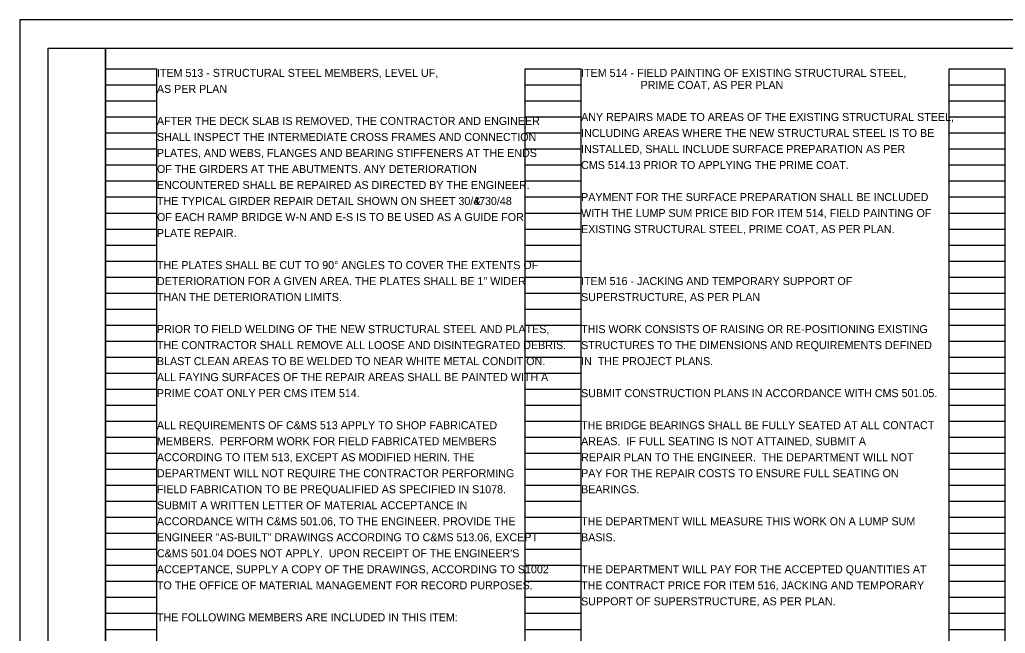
# Model space of a CAD drawing. Extents: x 0 to 34, y 0 to 22.
# Drawn here: x 0 to 17.24, y 11.27 to 22 of the extents above; entities that cross this region are included whole.
import ezdxf

# ---------------------------------------------------------------- set-up
doc = ezdxf.new("R2010")
doc.units = 0
for name, color, linetype in [('BR_P_Gen_Text', 7, 'Continuous'), ('SH_Border', 7, 'Continuous'), ('SH_Cut_Line', 7, 'Continuous'), ('SH_Data', 7, 'Continuous'), ('SH_Text', 7, 'Continuous')]:
    doc.layers.add(name, color=color, linetype=linetype)

msp = doc.modelspace()

# ---------------------------------------------------------------- linework, layer by layer
at = {"layer": 'SH_Border'}
for points in [[(0.5, 21.5), (1.5, 21.5), (1.5, 0.5), (0.5, 0.5)], [(1.5, 21.5), (33.5, 21.5), (33.5, 0.5), (1.5, 0.5)]]:
    msp.add_lwpolyline(points, close=True, dxfattribs=at)
at = {"layer": 'SH_Cut_Line'}
msp.add_lwpolyline([(0, 0), (34, 0), (34, 22), (0, 22)], close=True, dxfattribs=at)
at = {"layer": 'SH_Data'}
for p, q in [((1.5, 0.98), (1.5, 21.14)), ((1.5, 21.14), (2.4, 21.14)), ((2.4, 0.98), (2.4, 21.14)), ((8.84, 0.98), (8.84, 21.14)), ((8.84, 21.14), (9.82, 21.14)), ((9.82, 0.98), (9.82, 21.14)), ((16.26, 0.98), (16.26, 21.14)), ((16.26, 21.14), (17.24, 21.14)), ((17.24, 0.98), (17.24, 21.14)), ((1.5, 20.86), (2.4, 20.86)), ((8.84, 20.86), (9.82, 20.86)), ((16.26, 20.86), (17.24, 20.86)), ((1.5, 20.58), (2.4, 20.58)), ((8.84, 20.58), (9.82, 20.58)), ((16.26, 20.58), (17.24, 20.58)), ((1.5, 20.3), (2.4, 20.3)), ((8.84, 20.3), (9.82, 20.3)), ((16.26, 20.3), (17.24, 20.3)), ((1.5, 20.02), (2.4, 20.02)), ((8.84, 20.02), (9.82, 20.02)), ((16.26, 20.02), (17.24, 20.02)), ((1.5, 19.74), (2.4, 19.74)), ((8.84, 19.74), (9.82, 19.74)), ((16.26, 19.74), (17.24, 19.74)), ((1.5, 19.46), (2.4, 19.46)), ((8.84, 19.46), (9.82, 19.46)), ((16.26, 19.46), (17.24, 19.46)), ((1.5, 19.18), (2.4, 19.18)), ((8.84, 19.18), (9.82, 19.18)), ((16.26, 19.18), (17.24, 19.18)), ((1.5, 18.9), (2.4, 18.9)), ((8.84, 18.9), (9.82, 18.9)), ((16.26, 18.9), (17.24, 18.9)), ((1.5, 18.62), (2.4, 18.62)), ((8.84, 18.62), (9.82, 18.62)), ((16.26, 18.62), (17.24, 18.62)), ((1.5, 18.34), (2.4, 18.34)), ((8.84, 18.34), (9.82, 18.34)), ((16.26, 18.34), (17.24, 18.34)), ((1.5, 18.06), (2.4, 18.06)), ((8.84, 18.06), (9.82, 18.06)), ((16.26, 18.06), (17.24, 18.06)), ((1.5, 17.78), (2.4, 17.78)), ((8.84, 17.78), (9.82, 17.78)), ((16.26, 17.78), (17.24, 17.78)), ((1.5, 17.5), (2.4, 17.5)), ((8.84, 17.5), (9.82, 17.5)), ((16.26, 17.5), (17.24, 17.5)), ((1.5, 17.22), (2.4, 17.22)), ((8.84, 17.22), (9.82, 17.22)), ((16.26, 17.22), (17.24, 17.22)), ((1.5, 16.94), (2.4, 16.94)), ((8.84, 16.94), (9.82, 16.94)), ((16.26, 16.94), (17.24, 16.94)), ((1.5, 16.66), (2.4, 16.66)), ((8.84, 16.66), (9.82, 16.66)), ((16.26, 16.66), (17.24, 16.66)), ((1.5, 16.38), (2.4, 16.38)), ((8.84, 16.38), (9.82, 16.38)), ((16.26, 16.38), (17.24, 16.38)), ((1.5, 16.1), (2.4, 16.1)), ((8.84, 16.1), (9.82, 16.1)), ((16.26, 16.1), (17.24, 16.1)), ((1.5, 15.82), (2.4, 15.82)), ((8.84, 15.82), (9.82, 15.82)), ((16.26, 15.82), (17.24, 15.82)), ((1.5, 15.54), (2.4, 15.54)), ((8.84, 15.54), (9.82, 15.54)), ((16.26, 15.54), (17.24, 15.54)), ((1.5, 15.26), (2.4, 15.26)), ((8.84, 15.26), (9.82, 15.26)), ((16.26, 15.26), (17.24, 15.26)), ((1.5, 14.98), (2.4, 14.98)), ((8.84, 14.98), (9.82, 14.98)), ((16.26, 14.98), (17.24, 14.98)), ((1.5, 14.7), (2.4, 14.7)), ((8.84, 14.7), (9.82, 14.7)), ((16.26, 14.7), (17.24, 14.7)), ((1.5, 14.42), (2.4, 14.42)), ((8.84, 14.42), (9.82, 14.42)), ((16.26, 14.42), (17.24, 14.42)), ((1.5, 14.14), (2.4, 14.14)), ((8.84, 14.14), (9.82, 14.14)), ((16.26, 14.14), (17.24, 14.14)), ((1.5, 13.86), (2.4, 13.86)), ((8.84, 13.86), (9.82, 13.86)), ((16.26, 13.86), (17.24, 13.86)), ((1.5, 13.58), (2.4, 13.58)), ((8.84, 13.58), (9.82, 13.58)), ((16.26, 13.58), (17.24, 13.58)), ((1.5, 13.3), (2.4, 13.3)), ((8.84, 13.3), (9.82, 13.3)), ((16.26, 13.3), (17.24, 13.3)), ((1.5, 13.02), (2.4, 13.02)), ((8.84, 13.02), (9.82, 13.02)), ((16.26, 13.02), (17.24, 13.02)), ((1.5, 12.74), (2.4, 12.74)), ((8.84, 12.74), (9.82, 12.74)), ((16.26, 12.74), (17.24, 12.74)), ((1.5, 12.46), (2.4, 12.46)), ((8.84, 12.46), (9.82, 12.46)), ((16.26, 12.46), (17.24, 12.46)), ((1.5, 12.18), (2.4, 12.18)), ((8.84, 12.18), (9.82, 12.18)), ((16.26, 12.18), (17.24, 12.18)), ((1.5, 11.9), (2.4, 11.9)), ((8.84, 11.9), (9.82, 11.9)), ((16.26, 11.9), (17.24, 11.9)), ((1.5, 11.62), (2.4, 11.62)), ((8.84, 11.62), (9.82, 11.62)), ((16.26, 11.62), (17.24, 11.62)), ((1.5, 11.34), (2.4, 11.34)), ((8.84, 11.34), (9.82, 11.34)), ((16.26, 11.34), (17.24, 11.34))]:
    msp.add_line(p, q, dxfattribs=at)

# ---------------------------------------------------------------- texts
at = {"layer": 'BR_P_Gen_Text'}
for s, p in [('AFTER THE DECK SLAB IS REMOVED, THE CONTRACTOR AND ENGINEER ', (2.4, 20.16)), ('SHALL INSPECT THE INTERMEDIATE CROSS FRAMES AND CONNECTION ', (2.4, 19.88)), ('PLATES, AND WEBS, FLANGES AND BEARING STIFFENERS AT THE ENDS ', (2.4, 19.6)), ('OF THE GIRDERS AT THE ABUTMENTS. ANY DETERIORATION ', (2.4, 19.32)), ('ENCOUNTERED SHALL BE REPAIRED AS DIRECTED BY THE ENGINEER. ', (2.4, 19.04)), ('THE TYPICAL GIRDER REPAIR DETAIL SHOWN ON SHEET 30/47', (2.4, 18.76)), (' &', (7.887, 18.76)), (' 30/48 ', (8.087, 18.76)), ('OF EACH RAMP BRIDGE W-N AND E-S IS TO BE USED AS A GUIDE FOR ', (2.4, 18.48)), ('PLATE REPAIR.', (2.4, 18.2)), ('THE PLATES SHALL BE CUT TO 90° ANGLES TO COVER THE EXTENTS OF ', (2.4, 17.64)), ('DETERIORATION FOR A GIVEN AREA. THE PLATES SHALL BE 1" WIDER ', (2.4, 17.36)), ('THAN THE DETERIORATION LIMITS. ', (2.4, 17.08)), ('PRIOR TO FIELD WELDING OF THE NEW STRUCTURAL STEEL AND PLATES, ', (2.4, 16.52)), ('THE CONTRACTOR SHALL REMOVE ALL LOOSE AND DISINTEGRATED DEBRIS.  ', (2.4, 16.24)), ('BLAST CLEAN AREAS TO BE WELDED TO NEAR WHITE METAL CONDITION. ', (2.4, 15.96)), ('ALL FAYING SURFACES OF THE REPAIR AREAS SHALL BE PAINTED WITH A ', (2.4, 15.68)), ('PRIME COAT ONLY PER CMS ITEM 514.', (2.4, 15.4))]:
    msp.add_text(s, height=0.14, dxfattribs=at).set_placement(p)
at = {"layer": 'SH_Text'}
for s, p in [('ITEM 513 - STRUCTURAL STEEL MEMBERS, LEVEL UF,', (2.4, 21)), ('ITEM 514 - FIELD PAINTING OF EXISTING STRUCTURAL STEEL, ', (9.82, 21)), ('AS PER PLAN  ', (2.4, 20.72)), ('                    PRIME COAT, AS PER PLAN', (9.82, 20.79)), ('ANY REPAIRS MADE TO AREAS OF THE EXISTING STRUCTURAL STEEL,', (9.82, 20.229)), ('INCLUDING AREAS WHERE THE NEW STRUCTURAL STEEL IS TO BE', (9.82, 19.949)), ('INSTALLED, SHALL INCLUDE SURFACE PREPARATION AS PER', (9.82, 19.669)), ('CMS 514.13 PRIOR TO APPLYING THE PRIME COAT.', (9.82, 19.389)), ('PAYMENT FOR THE SURFACE PREPARATION SHALL BE INCLUDED', (9.82, 18.829)), ('WITH THE LUMP SUM PRICE BID FOR ITEM 514, FIELD PAINTING OF ', (9.82, 18.549)), ('EXISTING STRUCTURAL STEEL, PRIME COAT, AS PER PLAN.', (9.82, 18.269)), ('ITEM 516 - JACKING AND TEMPORARY SUPPORT OF', (9.82, 17.36)), ('SUPERSTRUCTURE, AS PER PLAN  ', (9.82, 17.08)), ('THIS WORK CONSISTS OF RAISING OR RE-POSITIONING EXISTING', (9.82, 16.52)), ('STRUCTURES TO THE DIMENSIONS AND REQUIREMENTS DEFINED', (9.82, 16.24)), ('IN  THE PROJECT PLANS.', (9.82, 15.96)), ('SUBMIT CONSTRUCTION PLANS IN ACCORDANCE WITH CMS 501.05.', (9.82, 15.4)), ('ALL REQUIREMENTS OF C&MS 513 APPLY TO SHOP FABRICATED', (2.4, 14.84)), ('THE BRIDGE BEARINGS SHALL BE FULLY SEATED AT ALL CONTACT', (9.82, 14.84)), ('MEMBERS.  PERFORM WORK FOR FIELD FABRICATED MEMBERS', (2.4, 14.56)), ('AREAS.  IF FULL SEATING IS NOT ATTAINED, SUBMIT A', (9.82, 14.56)), ('ACCORDING TO ITEM 513, EXCEPT AS MODIFIED HERIN. THE', (2.4, 14.28)), ('REPAIR PLAN TO THE ENGINEER.  THE DEPARTMENT WILL NOT', (9.82, 14.28)), ('DEPARTMENT WILL NOT REQUIRE THE CONTRACTOR PERFORMING', (2.4, 14)), ('PAY FOR THE REPAIR COSTS TO ENSURE FULL SEATING ON', (9.82, 14)), ('FIELD FABRICATION TO BE PREQUALIFIED AS SPECIFIED IN S1078.', (2.4, 13.72)), ('BEARINGS.', (9.82, 13.72)), ('SUBMIT A WRITTEN LETTER OF MATERIAL ACCEPTANCE IN', (2.4, 13.44)), ('ACCORDANCE WITH C&MS 501.06, TO THE ENGINEER. PROVIDE THE', (2.4, 13.16)), ('THE DEPARTMENT WILL MEASURE THIS WORK ON A LUMP SUM', (9.82, 13.16)), ('ENGINEER "AS-BUILT" DRAWINGS ACCORDING TO C&MS 513.06, EXCEPT', (2.4, 12.88)), ('BASIS.', (9.82, 12.88)), ("C&MS 501.04 DOES NOT APPLY.  UPON RECEIPT OF THE ENGINEER'S", (2.4, 12.6)), ('ACCEPTANCE, SUPPLY A COPY OF THE DRAWINGS, ACCORDING TO S1002', (2.4, 12.32)), ('THE DEPARTMENT WILL PAY FOR THE ACCEPTED QUANTITIES AT', (9.82, 12.32)), ('TO THE OFFICE OF MATERIAL MANAGEMENT FOR RECORD PURPOSES.', (2.4, 12.04)), ('THE CONTRACT PRICE FOR ITEM 516, JACKING AND TEMPORARY', (9.82, 12.04)), ('SUPPORT OF SUPERSTRUCTURE, AS PER PLAN.', (9.82, 11.76)), ('THE FOLLOWING MEMBERS ARE INCLUDED IN THIS ITEM:', (2.4, 11.48))]:
    msp.add_text(s, height=0.14, dxfattribs=at).set_placement(p)

doc.saveas('drawing.dxf')
